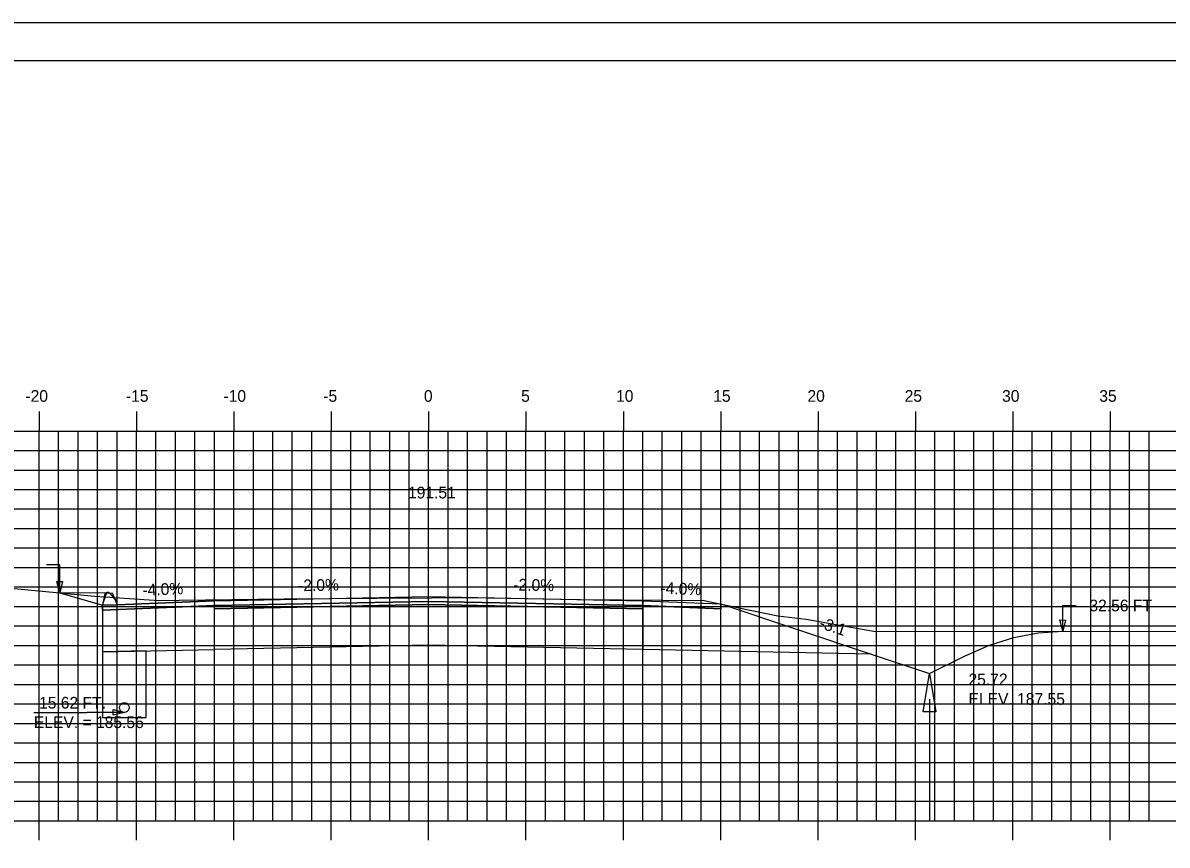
# Model space of a CAD drawing. Extents: x 1139207 to 1139377, y 608981 to 609091.
# Drawn here: x 1139268.9 to 1139327.6, y 609049.1 to 609091.3 of the extents above; entities that cross this region are included whole.
import ezdxf

# ---------------------------------------------------------------- set-up
doc = ezdxf.new("R2010")
doc.units = 0
for name, color, linetype in [('ANNOTATION', 7, 'Continuous'), ('BORDER', 7, 'Continuous'), ('D_Curb_Type_3M2_Lt', 7, 'Continuous'), ('D_Drainage_Ditch_Line', 7, 'Continuous'), ('D_Drainage_Underdrain', 7, 'Continuous'), ('D_Drainage_Underdrain_06in', 7, 'Continuous'), ('D_Roadway_Centerline', 7, 'Continuous'), ('D_Roadway_Centerline_Text', 7, 'Continuous'), ('D_Roadway_Edge_Shoulder', 7, 'Continuous'), ('D_Roadway_Edge_TW', 7, 'Continuous'), ('D_Roadway_Pavement', 7, 'Continuous'), ('D_Roadway_SlopeLines', 7, 'Continuous'), ('D_Roadway_SubGrade', 7, 'Continuous'), ('D_Text_Standard', 7, 'Continuous'), ('H_V ANNOTATION', 7, 'Continuous'), ('MAJOR', 7, 'Continuous'), ('MINOR', 7, 'Continuous'), ('PLOT BOUNDARY', 7, 'Continuous'), ('S_Roadway_Centerline', 7, 'Continuous')]:
    doc.layers.add(name, color=color, linetype=linetype)

msp = doc.modelspace()

# ---------------------------------------------------------------- linework, layer by layer
msp.add_lwpolyline([(1139270.765, 609062.035), (1139272.955, 609061.394), (1139272.956, 609061.394), (1139273.16, 609062.023), (1139273.455, 609062.034), (1139273.705, 609061.424), (1139278.705, 609061.624), (1139289.705, 609061.844), (1139300.705, 609061.624), (1139304.705, 609061.464), (1139312.429, 609058.89), (1139315.429, 609057.89), (1139317.265, 609058.808), (1139318.515, 609059.355), (1139319.765, 609059.746), (1139321.015, 609059.981), (1139322.265, 609060.06)])
at = {"layer": 'BORDER'}
msp.add_lwpolyline([(1139214.705, 608984.335), (1139374.705, 608984.335), (1139374.705, 609089.335), (1139214.705, 609089.335)], close=True, dxfattribs=at)
at = {"layer": 'D_Curb_Type_3M2_Lt'}
for p, q in [((1139273.063, 609061.918), (1139272.955, 609061.424)), ((1139273.199, 609062.047), (1139273.204, 609062.047)), ((1139273.705, 609061.591), (1139273.351, 609061.993)), ((1139273.705, 609061.424), (1139273.705, 609061.591)), ((1139272.955, 609061.424), (1139273.705, 609061.424))]:
    msp.add_line(p, q, dxfattribs=at)
msp.add_arc((1139273.226, 609061.883), 0.167, 41.38705, 167.66476, dxfattribs=at)
at = {"layer": 'D_Drainage_Ditch_Line'}
msp.add_line((1139315.429, 609056.578), (1139315.428, 609050.334), dxfattribs=at)
msp.add_lwpolyline([(1139315.757, 609055.921), (1139315.101, 609055.921), (1139315.429, 609057.89)], close=True, dxfattribs=at)
at = {"layer": 'D_Drainage_Underdrain'}
msp.add_lwpolyline([(1139272.956, 609059.009), (1139272.956, 609055.644), (1139275.206, 609055.644), (1139275.206, 609059.054)], close=True, dxfattribs=at)
at = {"layer": 'D_Drainage_Underdrain_06in'}
msp.add_lwpolyline([(1139274.081, 609056.394), (1139274.158, 609056.382), (1139274.228, 609056.347), (1139274.283, 609056.291), (1139274.319, 609056.222), (1139274.331, 609056.144), (1139274.319, 609056.067), (1139274.283, 609055.997), (1139274.228, 609055.942), (1139274.158, 609055.907), (1139274.081, 609055.894), (1139274.004, 609055.907), (1139273.934, 609055.942), (1139273.879, 609055.997), (1139273.843, 609056.067), (1139273.831, 609056.144), (1139273.843, 609056.222), (1139273.879, 609056.291), (1139273.934, 609056.347), (1139274.004, 609056.382)], close=True, dxfattribs=at)
at = {"layer": 'D_Roadway_Edge_Shoulder'}
msp.add_lwpolyline([(1139278.705, 609061.624), (1139273.705, 609061.424), (1139272.956, 609061.394), (1139272.956, 609061.144), (1139278.705, 609061.374), (1139278.705, 609061.624)], dxfattribs=at)
msp.add_lwpolyline([(1139300.705, 609061.624), (1139304.705, 609061.464), (1139304.705, 609061.214), (1139300.705, 609061.374)], close=True, dxfattribs=at)
at = {"layer": 'D_Roadway_Edge_TW'}
msp.add_lwpolyline([(1139278.705, 609061.374), (1139278.705, 609061.624), (1139289.705, 609061.844), (1139300.705, 609061.624), (1139300.705, 609061.374), (1139289.705, 609061.594)], close=True, dxfattribs=at)
at = {"layer": 'D_Roadway_Pavement'}
msp.add_lwpolyline([(1139278.705, 609061.208), (1139278.705, 609061.374), (1139289.705, 609061.594), (1139300.705, 609061.374), (1139300.705, 609061.208), (1139289.705, 609061.428)], close=True, dxfattribs=at)
at = {"layer": 'D_Roadway_SlopeLines'}
for points in [[(1139273.16, 609062.023), (1139270.765, 609062.035)], [(1139315.429, 609057.89), (1139317.265, 609058.808), (1139318.515, 609059.355), (1139319.765, 609059.746), (1139321.015, 609059.981), (1139322.265, 609060.06)], [(1139312.429, 609058.89), (1139315.429, 609057.89)]]:
    msp.add_lwpolyline(points, dxfattribs=at)
at = {"layer": 'D_Roadway_SubGrade'}
for points in [[(1139272.955, 609060.394), (1139272.956, 609059.009), (1139278.705, 609059.124), (1139278.705, 609061.208), (1139278.705, 609061.374), (1139272.956, 609061.144), (1139272.956, 609061.394), (1139272.955, 609061.394)], [(1139278.705, 609061.208), (1139278.705, 609061.374), (1139272.956, 609061.144), (1139272.956, 609061.394), (1139272.955, 609061.394), (1139272.956, 609059.009), (1139278.705, 609059.124)], [(1139278.705, 609059.124), (1139278.705, 609061.208), (1139289.705, 609061.428), (1139300.705, 609061.208), (1139300.705, 609059.124), (1139289.705, 609059.344)], [(1139300.705, 609061.208), (1139300.705, 609061.374), (1139304.705, 609061.214), (1139304.705, 609061.464), (1139304.705, 609061.464), (1139312.429, 609058.89), (1139300.705, 609059.124)]]:
    msp.add_lwpolyline(points, close=True, dxfattribs=at)
at = {"layer": 'D_Text_Standard'}
msp.add_line((1139269.434, 609055.894), (1139272.152, 609055.894), dxfattribs=at)
for points in [[(1139270.765, 609062.035), (1139270.763, 609063.474), (1139270.083, 609063.474)], [(1139322.265, 609060.058), (1139322.279, 609061.382), (1139322.959, 609061.382)], [(1139274.081, 609055.894), (1139272.832, 609055.894), (1139272.152, 609055.894)]]:
    msp.add_lwpolyline(points, dxfattribs=at)
for points in [[(1139270.765, 609062.035), (1139270.618, 609062.617), (1139270.91, 609062.617)], [(1139322.265, 609060.058), (1139322.126, 609060.642), (1139322.417, 609060.638)], [(1139274.081, 609055.894), (1139273.499, 609055.749), (1139273.499, 609056.04)]]:
    msp.add_lwpolyline(points, close=True, dxfattribs=at)
at = {"layer": 'MAJOR'}
for p, q in [((1139269.705, 609071.337), (1139269.705, 609070.335)), ((1139274.705, 609071.337), (1139274.705, 609070.335)), ((1139279.705, 609071.337), (1139279.705, 609070.335)), ((1139284.705, 609071.337), (1139284.705, 609070.335)), ((1139289.705, 609071.337), (1139289.705, 609070.335)), ((1139294.705, 609071.337), (1139294.705, 609070.335)), ((1139299.705, 609071.337), (1139299.705, 609070.335)), ((1139304.705, 609071.337), (1139304.705, 609070.335)), ((1139309.705, 609071.337), (1139309.705, 609070.335)), ((1139314.705, 609071.337), (1139314.705, 609070.335)), ((1139319.705, 609071.337), (1139319.705, 609070.335)), ((1139324.705, 609071.337), (1139324.705, 609070.335)), ((1139219.705, 609070.335), (1139359.705, 609070.335)), ((1139219.705, 609070.335), (1139359.705, 609070.335)), ((1139269.705, 609050.335), (1139269.705, 609070.335)), ((1139274.705, 609050.335), (1139274.705, 609070.335)), ((1139279.705, 609050.335), (1139279.705, 609070.335)), ((1139284.705, 609050.335), (1139284.705, 609070.335)), ((1139289.705, 609050.335), (1139289.705, 609070.335)), ((1139294.705, 609050.335), (1139294.705, 609070.335)), ((1139299.705, 609050.335), (1139299.705, 609070.335)), ((1139304.705, 609050.335), (1139304.705, 609070.335)), ((1139309.705, 609050.335), (1139309.705, 609070.335)), ((1139314.705, 609050.335), (1139314.705, 609070.335)), ((1139319.705, 609050.335), (1139319.705, 609070.335)), ((1139324.705, 609050.335), (1139324.705, 609070.335)), ((1139219.705, 609065.335), (1139359.705, 609065.335)), ((1139219.705, 609060.335), (1139359.705, 609060.335)), ((1139219.705, 609055.335), (1139359.705, 609055.335)), ((1139219.705, 609050.335), (1139359.705, 609050.335)), ((1139219.705, 609050.335), (1139359.705, 609050.335)), ((1139269.705, 609049.333), (1139269.705, 609050.335)), ((1139274.705, 609049.333), (1139274.705, 609050.335)), ((1139279.705, 609049.333), (1139279.705, 609050.335)), ((1139284.705, 609049.333), (1139284.705, 609050.335)), ((1139289.705, 609049.333), (1139289.705, 609050.335)), ((1139294.705, 609049.333), (1139294.705, 609050.335)), ((1139299.705, 609049.333), (1139299.705, 609050.335)), ((1139304.705, 609049.333), (1139304.705, 609050.335)), ((1139309.705, 609049.333), (1139309.705, 609050.335)), ((1139314.705, 609049.333), (1139314.705, 609050.335)), ((1139319.705, 609049.333), (1139319.705, 609050.335)), ((1139324.705, 609049.333), (1139324.705, 609050.335))]:
    msp.add_line(p, q, dxfattribs=at)
at = {"layer": 'MINOR'}
for p, q in [((1139270.705, 609050.335), (1139270.705, 609070.335)), ((1139271.705, 609050.335), (1139271.705, 609070.335)), ((1139272.705, 609050.335), (1139272.705, 609070.335)), ((1139273.705, 609050.335), (1139273.705, 609070.335)), ((1139275.705, 609050.335), (1139275.705, 609070.335)), ((1139276.705, 609050.335), (1139276.705, 609070.335)), ((1139277.705, 609050.335), (1139277.705, 609070.335)), ((1139278.705, 609050.335), (1139278.705, 609070.335)), ((1139280.705, 609050.335), (1139280.705, 609070.335)), ((1139281.705, 609050.335), (1139281.705, 609070.335)), ((1139282.705, 609050.335), (1139282.705, 609070.335)), ((1139283.705, 609050.335), (1139283.705, 609070.335)), ((1139285.705, 609050.335), (1139285.705, 609070.335)), ((1139286.705, 609050.335), (1139286.705, 609070.335)), ((1139287.705, 609050.335), (1139287.705, 609070.335)), ((1139288.705, 609050.335), (1139288.705, 609070.335)), ((1139290.705, 609050.335), (1139290.705, 609070.335)), ((1139291.705, 609050.335), (1139291.705, 609070.335)), ((1139292.705, 609050.335), (1139292.705, 609070.335)), ((1139293.705, 609050.335), (1139293.705, 609070.335)), ((1139295.705, 609050.335), (1139295.705, 609070.335)), ((1139296.705, 609050.335), (1139296.705, 609070.335)), ((1139297.705, 609050.335), (1139297.705, 609070.335)), ((1139298.705, 609050.335), (1139298.705, 609070.335)), ((1139300.705, 609050.335), (1139300.705, 609070.335)), ((1139301.705, 609050.335), (1139301.705, 609070.335)), ((1139302.705, 609050.335), (1139302.705, 609070.335)), ((1139303.705, 609050.335), (1139303.705, 609070.335)), ((1139305.705, 609050.335), (1139305.705, 609070.335)), ((1139306.705, 609050.335), (1139306.705, 609070.335)), ((1139307.705, 609050.335), (1139307.705, 609070.335)), ((1139308.705, 609050.335), (1139308.705, 609070.335)), ((1139310.705, 609050.335), (1139310.705, 609070.335)), ((1139311.705, 609050.335), (1139311.705, 609070.335)), ((1139312.705, 609050.335), (1139312.705, 609070.335)), ((1139313.705, 609050.335), (1139313.705, 609070.335)), ((1139315.705, 609050.335), (1139315.705, 609070.335)), ((1139316.705, 609050.335), (1139316.705, 609070.335)), ((1139317.705, 609050.335), (1139317.705, 609070.335)), ((1139318.705, 609050.335), (1139318.705, 609070.335)), ((1139320.705, 609050.335), (1139320.705, 609070.335)), ((1139321.705, 609050.335), (1139321.705, 609070.335)), ((1139322.705, 609050.335), (1139322.705, 609070.335)), ((1139323.705, 609050.335), (1139323.705, 609070.335)), ((1139325.705, 609050.335), (1139325.705, 609070.335)), ((1139326.705, 609050.335), (1139326.705, 609070.335)), ((1139219.705, 609069.335), (1139359.705, 609069.335)), ((1139219.705, 609068.335), (1139359.705, 609068.335)), ((1139219.705, 609067.335), (1139359.705, 609067.335)), ((1139219.705, 609066.335), (1139359.705, 609066.335)), ((1139219.705, 609064.335), (1139359.705, 609064.335)), ((1139219.705, 609063.335), (1139359.705, 609063.335)), ((1139219.705, 609062.335), (1139359.705, 609062.335)), ((1139219.705, 609061.335), (1139359.705, 609061.335)), ((1139219.705, 609059.335), (1139359.705, 609059.335)), ((1139219.705, 609058.335), (1139359.705, 609058.335)), ((1139219.705, 609057.335), (1139359.705, 609057.335)), ((1139219.705, 609056.335), (1139359.705, 609056.335)), ((1139219.705, 609054.335), (1139359.705, 609054.335)), ((1139219.705, 609053.335), (1139359.705, 609053.335)), ((1139219.705, 609052.335), (1139359.705, 609052.335)), ((1139219.705, 609051.335), (1139359.705, 609051.335))]:
    msp.add_line(p, q, dxfattribs=at)
at = {"layer": 'PLOT BOUNDARY'}
msp.add_lwpolyline([(1139206.612, 608981.276), (1139376.612, 608981.276), (1139376.612, 609091.276), (1139206.612, 609091.276)], close=True, dxfattribs=at)
at = {"layer": 'S_Roadway_Centerline'}
msp.add_lwpolyline([(1139231.693, 609064.2), (1139235.188, 609064.142), (1139236.871, 609064.001), (1139239.489, 609063.871), (1139241.838, 609063.755), (1139250.238, 609063.378), (1139264.143, 609062.648), (1139264.256, 609062.641), (1139272.57, 609061.866), (1139275.873, 609061.633), (1139276.892, 609061.652), (1139282.291, 609061.733), (1139287.04, 609061.756), (1139292.681, 609061.794), (1139292.709, 609061.781), (1139297.486, 609061.69), (1139303.847, 609061.636), (1139305.717, 609061.239), (1139307.637, 609060.852), (1139309.089, 609060.674), (1139312.659, 609060.053), (1139353.311, 609060.081), (1139359.705, 609060.02)], dxfattribs=at)

# ---------------------------------------------------------------- texts
at = {"layer": 'ANNOTATION'}
for s, rotation, p in [('-2.0%', 1.14576, (1139283.008, 609062.111)), ('-2.0%', 358.85424, (1139294.048, 609062.158)), ('-4.0%', 2.29061, (1139275.021, 609061.878)), ('-4.0%', 357.70939, (1139301.601, 609061.989)), ('-3:1', 341.56521, (1139309.717, 609060.248))]:
    msp.add_text(s, height=0.6, rotation=rotation, dxfattribs=at).set_placement(p)
at = {"layer": 'D_Roadway_Centerline'}
for s, p in [('C', (1139289.7, 609061.844)), ('L', (1139289.705, 609061.837))]:
    msp.add_text(s, height=0.0146, dxfattribs=at).set_placement(p)
at = {"layer": 'D_Roadway_Centerline_Text'}
msp.add_text('191.51', height=0.6, dxfattribs=at).set_placement((1139288.646, 609066.876))
at = {"layer": 'D_Text_Standard'}
for s, p in [('32.56 FT', (1139323.639, 609061.082)), ('25.72', (1139317.429, 609057.29)), ('ELEV. 187.55', (1139317.429, 609056.288)), ('-15.62 FT.', (1139269.434, 609056.094)), ('ELEV. = 185.56', (1139269.434, 609055.094))]:
    msp.add_text(s, height=0.6, dxfattribs=at).set_placement(p)
at = {"layer": 'H_V ANNOTATION'}
for s, p in [('-20', (1139268.999, 609071.835)), ('-15', (1139274.162, 609071.835)), ('-10', (1139279.17, 609071.835)), ('-5', (1139284.296, 609071.835)), ('0', (1139289.464, 609071.835)), ('5', (1139294.456, 609071.835)), ('10', (1139299.331, 609071.835)), ('15', (1139304.323, 609071.835)), ('20', (1139309.159, 609071.835)), ('25', (1139314.151, 609071.835)), ('30', (1139319.154, 609071.835)), ('35', (1139324.146, 609071.835))]:
    msp.add_text(s, height=0.6, dxfattribs=at).set_placement(p)
at = {"layer": 'S_Roadway_Centerline'}
for s, p in [('C', (1139292.676, 609061.794)), ('L', (1139292.681, 609061.786))]:
    msp.add_text(s, height=0.0146, dxfattribs=at).set_placement(p)

doc.saveas('drawing.dxf')
